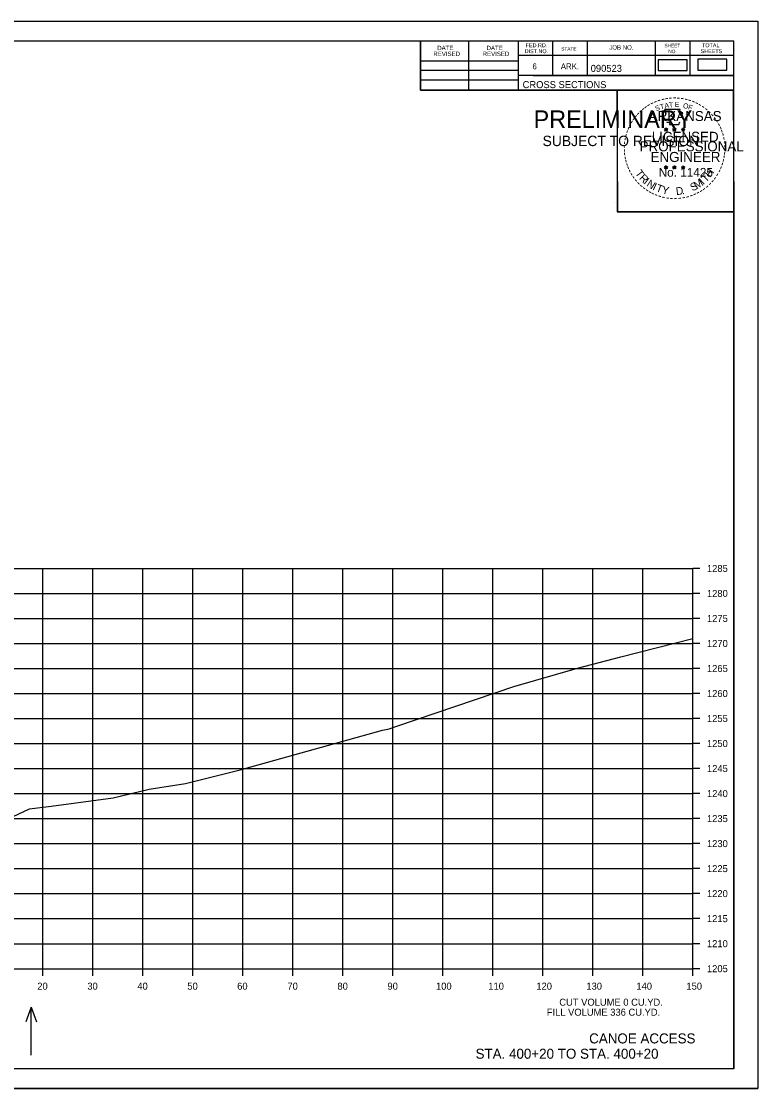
# Model space of a CAD drawing. Extents: x 1406028 to 1412453, y 321733 to 325986.
# Drawn here: x 1411799 to 1411946.2, y 322044.9 to 322258.3 of the extents above; entities that cross this region are included whole.
import ezdxf

# ---------------------------------------------------------------- set-up
doc = ezdxf.new("R2010")
doc.units = 0
for name, color, linetype in [('R_Axis', 7, 'Continuous'), ('R_Axis Annot', 7, 'Continuous'), ('R_Border', 7, 'Continuous'), ('R_Border PE', 7, 'Continuous'), ('R_Border Prem', 7, 'Continuous'), ('R_Draft', 7, 'Continuous'), ('R_Exist Surface', 7, 'Continuous'), ('R_Fin Surface', 7, 'Continuous'), ('R_Grid', 7, 'Continuous'), ('R_No Plot', 7, 'Continuous'), ('R_Water Annot', 7, 'Continuous')]:
    doc.layers.add(name, color=color, linetype=linetype)

msp = doc.modelspace()

# ---------------------------------------------------------------- linework, layer by layer
at = {"layer": 'R_Axis'}
for p, q in [((1411933.24, 322068.91), (1411933.24, 322148.91)), ((1411934.64, 322148.91), (1411933.24, 322148.91)), ((1411934.64, 322143.91), (1411933.24, 322143.91)), ((1411934.64, 322138.91), (1411933.24, 322138.91)), ((1411934.64, 322133.91), (1411933.24, 322133.91)), ((1411934.64, 322128.91), (1411933.24, 322128.91)), ((1411934.64, 322123.91), (1411933.24, 322123.91)), ((1411934.64, 322118.91), (1411933.24, 322118.91)), ((1411934.64, 322113.91), (1411933.24, 322113.91)), ((1411934.64, 322108.91), (1411933.24, 322108.91)), ((1411934.64, 322103.91), (1411933.24, 322103.91)), ((1411934.64, 322098.91), (1411933.24, 322098.91)), ((1411934.64, 322093.91), (1411933.24, 322093.91)), ((1411934.64, 322088.91), (1411933.24, 322088.91)), ((1411934.64, 322083.91), (1411933.24, 322083.91)), ((1411934.64, 322078.91), (1411933.24, 322078.91)), ((1411934.64, 322073.91), (1411933.24, 322073.91)), ((1411633.24, 322068.91), (1411933.24, 322068.91)), ((1411803.24, 322067.51), (1411803.24, 322068.91)), ((1411813.24, 322067.51), (1411813.24, 322068.91)), ((1411823.24, 322067.51), (1411823.24, 322068.91)), ((1411833.24, 322067.51), (1411833.24, 322068.91)), ((1411843.24, 322067.51), (1411843.24, 322068.91)), ((1411853.24, 322067.51), (1411853.24, 322068.91)), ((1411863.24, 322067.51), (1411863.24, 322068.91)), ((1411873.24, 322067.51), (1411873.24, 322068.91)), ((1411883.24, 322067.51), (1411883.24, 322068.91)), ((1411893.24, 322067.51), (1411893.24, 322068.91)), ((1411903.24, 322067.51), (1411903.24, 322068.91)), ((1411913.24, 322067.51), (1411913.24, 322068.91)), ((1411923.24, 322067.51), (1411923.24, 322068.91)), ((1411933.24, 322067.51), (1411933.24, 322068.91)), ((1411934.64, 322068.91), (1411933.24, 322068.91))]:
    msp.add_line(p, q, dxfattribs=at)
at = {"layer": 'R_Border'}
for p, q in [((1411625.24, 322254.37), (1411941.42, 322254.37)), ((1411878.78, 322244.49), (1411878.78, 322254.37)), ((1411888.46, 322244.49), (1411888.46, 322254.37)), ((1411898.32, 322254.37), (1411898.32, 322244.49)), ((1411905.16, 322254.37), (1411905.16, 322247.43)), ((1411912.1, 322254.37), (1411912.1, 322247.43)), ((1411925.68, 322254.37), (1411925.68, 322247.43)), ((1411932.62, 322254.37), (1411932.62, 322247.43)), ((1411941.42, 322048.91), (1411941.42, 322254.37)), ((1411941.42, 322251.43), (1411898.32, 322251.43)), ((1411941.42, 322251.45), (1411941.42, 322251.45)), ((1411878.78, 322250.35), (1411898.32, 322250.35)), ((1411878.78, 322248.49), (1411898.32, 322248.49)), ((1411878.78, 322246.55), (1411898.32, 322246.55)), ((1411941.42, 322247.43), (1411898.32, 322247.43)), ((1411901.28, 322247.43), (1411941.42, 322247.43)), ((1411941.42, 322244.49), (1411878.78, 322244.49)), ((1411941.42, 322048.91), (1411625.24, 322048.91))]:
    msp.add_line(p, q, dxfattribs=at)
at = {"layer": 'R_Border PE'}
for p, q in [((1411927.51, 322236.75), (1411927.86, 322236.64)), ((1411927.51, 322236.75), (1411927.76, 322236.7)), ((1411927.51, 322236.75), (1411927.75, 322236.63)), ((1411927.64, 322236.34), (1411927.86, 322236.64)), ((1411927.64, 322236.34), (1411927.77, 322236.58)), ((1411927.64, 322236.34), (1411927.86, 322236.56)), ((1411927.86, 322237), (1411927.82, 322236.75)), ((1411927.86, 322236.64), (1411927.86, 322237)), ((1411927.86, 322237), (1411927.91, 322236.75)), ((1411928.2, 322236.75), (1411927.86, 322236.64)), ((1411928.07, 322236.34), (1411927.86, 322236.64)), ((1411928.07, 322236.34), (1411927.86, 322236.55)), ((1411928.2, 322236.75), (1411927.92, 322236.7)), ((1411928.07, 322236.34), (1411927.93, 322236.63)), ((1411928.2, 322236.75), (1411928, 322236.65)), ((1411929.18, 322236.75), (1411929.53, 322236.64)), ((1411929.18, 322236.75), (1411929.43, 322236.7)), ((1411929.18, 322236.75), (1411929.42, 322236.63)), ((1411929.31, 322236.34), (1411929.53, 322236.64)), ((1411929.31, 322236.34), (1411929.44, 322236.58)), ((1411929.31, 322236.34), (1411929.53, 322236.56)), ((1411929.53, 322237), (1411929.49, 322236.75)), ((1411929.53, 322236.64), (1411929.53, 322237)), ((1411929.53, 322237), (1411929.58, 322236.75)), ((1411929.87, 322236.75), (1411929.53, 322236.64)), ((1411929.74, 322236.34), (1411929.53, 322236.64)), ((1411929.74, 322236.34), (1411929.53, 322236.55)), ((1411929.87, 322236.75), (1411929.59, 322236.7)), ((1411929.74, 322236.34), (1411929.6, 322236.63)), ((1411929.87, 322236.75), (1411929.67, 322236.65)), ((1411930.94, 322236.74), (1411931.29, 322236.62)), ((1411930.94, 322236.74), (1411931.2, 322236.69)), ((1411930.94, 322236.74), (1411931.18, 322236.61)), ((1411931.08, 322236.33), (1411931.29, 322236.62)), ((1411931.08, 322236.33), (1411931.2, 322236.57)), ((1411931.08, 322236.33), (1411931.29, 322236.54)), ((1411931.29, 322236.99), (1411931.25, 322236.74)), ((1411931.29, 322236.62), (1411931.29, 322236.99)), ((1411931.29, 322236.99), (1411931.34, 322236.74)), ((1411931.64, 322236.74), (1411931.29, 322236.62)), ((1411931.5, 322236.33), (1411931.29, 322236.62)), ((1411931.5, 322236.33), (1411931.29, 322236.54)), ((1411931.64, 322236.74), (1411931.35, 322236.69)), ((1411931.5, 322236.33), (1411931.37, 322236.62)), ((1411931.64, 322236.74), (1411931.43, 322236.63)), ((1411927.85, 322229.43), (1411927.81, 322229.18)), ((1411927.85, 322229.06), (1411927.85, 322229.43)), ((1411927.85, 322229.43), (1411927.9, 322229.18)), ((1411929.52, 322229.43), (1411929.48, 322229.18)), ((1411929.52, 322229.06), (1411929.52, 322229.43)), ((1411929.52, 322229.43), (1411929.57, 322229.18)), ((1411931.29, 322229.42), (1411931.25, 322229.17)), ((1411931.29, 322229.05), (1411931.29, 322229.42)), ((1411931.29, 322229.42), (1411931.34, 322229.17)), ((1411927.5, 322229.17), (1411927.85, 322229.06)), ((1411927.5, 322229.17), (1411927.76, 322229.13)), ((1411927.5, 322229.17), (1411927.74, 322229.05)), ((1411927.64, 322228.77), (1411927.85, 322229.06)), ((1411927.64, 322228.77), (1411927.76, 322229.01)), ((1411927.64, 322228.77), (1411927.85, 322228.98)), ((1411928.2, 322229.17), (1411927.85, 322229.06)), ((1411928.07, 322228.77), (1411927.85, 322229.06)), ((1411928.07, 322228.77), (1411927.85, 322228.98)), ((1411928.2, 322229.17), (1411927.91, 322229.13)), ((1411928.07, 322228.77), (1411927.93, 322229.06)), ((1411928.2, 322229.17), (1411928, 322229.07)), ((1411929.17, 322229.17), (1411929.52, 322229.06)), ((1411929.17, 322229.17), (1411929.43, 322229.13)), ((1411929.17, 322229.17), (1411929.41, 322229.05)), ((1411929.31, 322228.77), (1411929.52, 322229.06)), ((1411929.31, 322228.77), (1411929.43, 322229.01)), ((1411929.31, 322228.77), (1411929.52, 322228.98)), ((1411929.87, 322229.17), (1411929.52, 322229.06)), ((1411929.74, 322228.77), (1411929.52, 322229.06)), ((1411929.74, 322228.77), (1411929.52, 322228.98)), ((1411929.87, 322229.17), (1411929.58, 322229.13)), ((1411929.74, 322228.77), (1411929.6, 322229.06)), ((1411929.87, 322229.17), (1411929.67, 322229.07)), ((1411930.94, 322229.16), (1411931.29, 322229.05)), ((1411930.94, 322229.16), (1411931.19, 322229.12)), ((1411930.94, 322229.16), (1411931.18, 322229.04)), ((1411931.07, 322228.76), (1411931.29, 322229.05)), ((1411931.07, 322228.76), (1411931.2, 322229)), ((1411931.07, 322228.76), (1411931.29, 322228.97)), ((1411931.64, 322229.16), (1411931.29, 322229.05)), ((1411931.5, 322228.76), (1411931.29, 322229.05)), ((1411931.5, 322228.76), (1411931.29, 322228.97)), ((1411931.64, 322229.16), (1411931.35, 322229.12)), ((1411931.5, 322228.76), (1411931.37, 322229.05)), ((1411931.64, 322229.16), (1411931.43, 322229.06))]:
    msp.add_line(p, q, dxfattribs=at)
for points in [[(1411927.55, 322240.63), (1411927.82, 322239.8)], [(1411931.06, 322239.7), (1411931.2, 322239.99), (1411930.52, 322239.96), (1411930.67, 322240.63), (1411927.55, 322240.63)], [(1411928.04, 322238.2), (1411928.04, 322238.12), (1411928.6, 322238.1), (1411928.55, 322237.62), (1411930.42, 322237.62), (1411930.62, 322238.16)], [(1411927.86, 322237), (1411928.07, 322236.34), (1411927.51, 322236.75), (1411928.2, 322236.75), (1411927.64, 322236.34), (1411927.86, 322237)], [(1411929.53, 322237), (1411929.74, 322236.34), (1411929.18, 322236.75), (1411929.87, 322236.75), (1411929.31, 322236.34), (1411929.53, 322237)], [(1411931.29, 322236.99), (1411931.5, 322236.33), (1411930.94, 322236.74), (1411931.64, 322236.74), (1411931.08, 322236.33), (1411931.29, 322236.99)], [(1411927.85, 322229.43), (1411928.07, 322228.77), (1411927.5, 322229.17), (1411928.2, 322229.17), (1411927.64, 322228.77), (1411927.85, 322229.43)], [(1411929.52, 322229.43), (1411929.74, 322228.77), (1411929.17, 322229.17), (1411929.87, 322229.17), (1411929.31, 322228.77), (1411929.52, 322229.43)], [(1411931.29, 322229.42), (1411931.5, 322228.76), (1411930.94, 322229.16), (1411931.64, 322229.16), (1411931.07, 322228.76), (1411931.29, 322229.42)]]:
    msp.add_lwpolyline(points, dxfattribs=at)
for centre, radius in [((1411927.86, 322236.64), 0.172), ((1411927.86, 322236.64), 0.145), ((1411927.86, 322236.64), 0.116), ((1411927.86, 322236.64), 0.0991), ((1411927.86, 322236.64), 0.0747), ((1411927.86, 322236.64), 0.0495), ((1411927.86, 322236.64), 0.0296), ((1411929.53, 322236.64), 0.172), ((1411929.53, 322236.64), 0.145), ((1411929.53, 322236.64), 0.116), ((1411929.53, 322236.64), 0.0991), ((1411929.53, 322236.64), 0.0747), ((1411929.53, 322236.64), 0.0495), ((1411929.53, 322236.64), 0.0296), ((1411931.29, 322236.62), 0.172), ((1411931.29, 322236.62), 0.145), ((1411931.29, 322236.62), 0.116), ((1411931.29, 322236.62), 0.0991), ((1411931.29, 322236.62), 0.0747), ((1411931.29, 322236.62), 0.0495), ((1411931.29, 322236.62), 0.0296), ((1411927.85, 322229.06), 0.172), ((1411927.85, 322229.06), 0.145), ((1411927.85, 322229.06), 0.116), ((1411927.85, 322229.06), 0.0991), ((1411927.85, 322229.06), 0.0747), ((1411927.85, 322229.06), 0.0495), ((1411927.85, 322229.06), 0.0296), ((1411929.52, 322229.06), 0.172), ((1411929.52, 322229.06), 0.145), ((1411929.52, 322229.06), 0.116), ((1411929.52, 322229.06), 0.0991), ((1411929.52, 322229.06), 0.0747), ((1411929.52, 322229.06), 0.0495), ((1411929.52, 322229.06), 0.0296), ((1411931.29, 322229.05), 0.172), ((1411931.29, 322229.05), 0.145), ((1411931.29, 322229.05), 0.116), ((1411931.29, 322229.05), 0.0991), ((1411931.29, 322229.05), 0.0747), ((1411931.29, 322229.05), 0.0495), ((1411931.29, 322229.05), 0.0296)]:
    msp.add_circle(centre, radius, dxfattribs=at)
at = {"layer": 'R_Exist Surface'}
msp.add_lwpolyline([(1411786.04, 322094.07), (1411800.57, 322100.83), (1411804.9, 322101.41), (1411817.35, 322103.05), (1411824.51, 322104.81), (1411831.82, 322105.92), (1411842.7, 322108.67), (1411871.19, 322116.61), (1411872.21, 322116.81), (1411872.49, 322116.86), (1411874.06, 322117.41), (1411897.46, 322125.32), (1411910.16, 322128.99), (1411918.81, 322131.24), (1411933.24, 322134.92)], dxfattribs=at)
at = {"layer": 'R_Fin Surface'}
for points in [[(1411934.19, 322248.54), (1411940.02, 322248.54), (1411940.02, 322250.73), (1411934.19, 322250.73)], [(1411926.28, 322248.42), (1411932.11, 322248.42), (1411932.11, 322250.6), (1411926.28, 322250.6)]]:
    msp.add_lwpolyline(points, close=True, dxfattribs=at)
at = {"layer": 'R_Grid'}
for p, q in [((1411633.24, 322148.91), (1411933.24, 322148.91)), ((1411803.24, 322068.91), (1411803.24, 322148.91)), ((1411813.24, 322068.91), (1411813.24, 322148.91)), ((1411823.24, 322068.91), (1411823.24, 322148.91)), ((1411833.24, 322068.91), (1411833.24, 322148.91)), ((1411843.24, 322068.91), (1411843.24, 322148.91)), ((1411853.24, 322068.91), (1411853.24, 322148.91)), ((1411863.24, 322068.91), (1411863.24, 322148.91)), ((1411873.24, 322068.91), (1411873.24, 322148.91)), ((1411883.24, 322068.91), (1411883.24, 322148.91)), ((1411893.24, 322068.91), (1411893.24, 322148.91)), ((1411903.24, 322068.91), (1411903.24, 322148.91)), ((1411913.24, 322068.91), (1411913.24, 322148.91)), ((1411923.24, 322068.91), (1411923.24, 322148.91)), ((1411933.24, 322068.91), (1411933.24, 322148.91)), ((1411633.24, 322143.91), (1411933.24, 322143.91)), ((1411633.24, 322138.91), (1411933.24, 322138.91)), ((1411633.24, 322133.91), (1411933.24, 322133.91)), ((1411633.24, 322128.91), (1411933.24, 322128.91)), ((1411633.24, 322123.91), (1411933.24, 322123.91)), ((1411633.24, 322118.91), (1411933.24, 322118.91)), ((1411633.24, 322113.91), (1411933.24, 322113.91)), ((1411633.24, 322108.91), (1411933.24, 322108.91)), ((1411633.24, 322103.91), (1411933.24, 322103.91)), ((1411633.24, 322098.91), (1411933.24, 322098.91)), ((1411633.24, 322093.91), (1411933.24, 322093.91)), ((1411633.24, 322088.91), (1411933.24, 322088.91)), ((1411633.24, 322083.91), (1411933.24, 322083.91)), ((1411633.24, 322078.91), (1411933.24, 322078.91)), ((1411633.24, 322073.91), (1411933.24, 322073.91)), ((1411633.24, 322068.91), (1411933.24, 322068.91))]:
    msp.add_line(p, q, dxfattribs=at)
at = {"layer": 'R_No Plot'}
for p, q in [((1411612.84, 322258.27), (1411946.18, 322258.27)), ((1411917.46, 322222.04), (1411917.46, 322222.04)), ((1411612.84, 322044.93), (1411946.18, 322044.93))]:
    msp.add_line(p, q, dxfattribs=at)
for points in [[(1411612.84, 322258.27), (1411946.18, 322258.27), (1411946.18, 322044.93), (1411612.84, 322044.93)], [(1411859.16, 322254.37), (1411878.78, 322254.37), (1411878.78, 322244.49), (1411894.9, 322244.49), (1411918.1, 322244.49), (1411918.1, 322220.16), (1411941.42, 322220.16), (1411941.42, 322048.91), (1411625.24, 322048.91), (1411625.24, 322254.37)], [(1411918.1, 322244.49), (1411941.3, 322244.49), (1411941.42, 322220.16), (1411918.22, 322220.16)]]:
    msp.add_lwpolyline(points, close=True, dxfattribs=at)
at = {"layer": 'R_Water Annot'}
for p, q in [((1411800.93, 322061.19), (1411799.87, 322058.26)), ((1411800.93, 322051.61), (1411800.93, 322061.19)), ((1411800.93, 322061.19), (1411802, 322058.26))]:
    msp.add_line(p, q, dxfattribs=at)

# ---------------------------------------------------------------- texts
at = {"layer": 'R_Axis Annot'}
for s, p in [('1285', (1411936.04, 322148.21)), ('1280', (1411936.04, 322143.21)), ('1275', (1411936.04, 322138.21)), ('1270', (1411936.04, 322133.21)), ('1265', (1411936.04, 322128.21)), ('1260', (1411936.04, 322123.21)), ('1255', (1411936.04, 322118.21)), ('1250', (1411936.04, 322113.21)), ('1245', (1411936.04, 322108.21)), ('1240', (1411936.04, 322103.21)), ('1235', (1411936.04, 322098.21)), ('1230', (1411936.04, 322093.21)), ('1225', (1411936.04, 322088.21)), ('1220', (1411936.04, 322083.21)), ('1215', (1411936.04, 322078.21)), ('1210', (1411936.04, 322073.21)), ('1205', (1411936.04, 322068.21)), ('20', (1411802.16, 322064.71)), ('30', (1411812.16, 322064.71)), ('40', (1411822.16, 322064.71)), ('50', (1411832.16, 322064.71)), ('60', (1411842.12, 322064.71)), ('70', (1411852.16, 322064.71)), ('80', (1411862.16, 322064.71)), ('90', (1411872.16, 322064.71)), ('100', (1411881.87, 322064.71)), ('110', (1411892.32, 322064.71)), ('120', (1411901.93, 322064.71)), ('130', (1411911.93, 322064.71)), ('140', (1411921.93, 322064.71)), ('150', (1411931.93, 322064.71)), ('FILL VOLUME 336 CU.YD.', (1411904.01, 322059.51)), ('CUT VOLUME 0 CU.YD.', (1411906.52, 322061.51))]:
    msp.add_text(s, height=1.4, dxfattribs=at).set_placement(p)
at = {"layer": 'R_Border'}
for s, height, p in [('DATE', 0.879, (1411882.12, 322252.51)), ('DATE', 0.879, (1411891.98, 322252.51)), ('FED.RD.', 0.782, (1411899.8, 322253.09)), ('STATE', 0.684, (1411906.92, 322252.41)), ('JOB NO.', 0.879, (1411916.5, 322252.61)), ('SHEET', 0.684, (1411927.54, 322253.09)), ('TOTAL', 0.782, (1411935.06, 322253.09)), ('REVISED', 0.879, (1411881.34, 322251.33)), ('REVISED', 0.879, (1411891.2, 322251.33)), ('DIST.NO.', 0.782, (1411899.6, 322251.91)), ('NO.', 0.684, (1411928.32, 322251.91)), ('SHEETS', 0.782, (1411934.78, 322251.91)), ('6', 1.17, (1411901.16, 322248.69)), ('ARK.', 1.172, (1411906.82, 322248.69)), ('090523', 1.4, (1411912.8, 322248.17)), ('CROSS SECTIONS', 1.4, (1411899.19, 322244.92))]:
    msp.add_text(s, height=height, rotation=360, dxfattribs=at).set_placement(p)
at = {"layer": 'R_Border PE'}
for s, height, rotation, p in [('-', 1.6, 24.3072, (1411925.66, 322241.48)), ('-', 1.6, 19.1761, (1411926.3, 322241.75)), ('-', 1.6, 13.6301, (1411927.05, 322241.99)), ('-', 1.6, 10.2193, (1411927.73, 322242.16)), ('-', 1.6, 5.8968, (1411928.45, 322242.27)), ('-', 1.6, 0.1862, (1411929.23, 322242.34)), ('-', 1.6, 357.743, (1411929.95, 322242.32)), ('-', 1.6, 352.1617, (1411930.69, 322242.27)), ('-', 1.6, 347.2049, (1411931.41, 322242.15)), ('-', 1.6, 342.3362, (1411932.05, 322242)), ('-', 1.6, 337.8551, (1411932.78, 322241.78)), ('-', 1.6, 48.423, (1411922.5, 322239.13)), ('-', 1.6, 42.9622, (1411922.95, 322239.61)), ('-', 1.6, 38.9507, (1411923.38, 322240.02)), ('-', 1.6, 36.2317, (1411923.86, 322240.4)), ('-', 1.6, 34.0636, (1411924.43, 322240.8)), ('ARKANSAS', 2, 360, (1411924.4, 322238.34)), ('-', 1.6, 28.7918, (1411925.03, 322241.17)), ('S', 1, 21.594, (1411925.9, 322240.3)), ('T', 1, 16.4036, (1411926.82, 322240.63)), ('A', 1, 11.2132, (1411927.64, 322240.89)), ('T', 1, 6.0228, (1411928.49, 322241.05)), ('E', 1, 0.8323, (1411929.6, 322241.16)), ('O', 1, 350.4515, (1411931.2, 322240.95)), ('F', 1, 340.0707, (1411932.16, 322240.72)), ('-', 1.6, 334.1211, (1411933.41, 322241.51)), ('-', 1.6, 329.6409, (1411933.99, 322241.22)), ('-', 1.6, 325.8627, (1411934.64, 322240.86)), ('-', 1.6, 320.5297, (1411935.25, 322240.44)), ('-', 1.6, 315.5786, (1411935.84, 322239.95)), ('-', 1.6, 58.0706, (1411921.36, 322237.55)), ('-', 1.6, 54.2325, (1411921.68, 322238.08)), ('-', 1.6, 50.6142, (1411922.1, 322238.64)), ('-', 1.6, 309.8797, (1411936.41, 322239.4)), ('-', 1.6, 306.6522, (1411936.94, 322238.8)), ('-', 1.4, 303.6753, (1411937.42, 322238.23)), ('-', 1.6, 72.3945, (1411920.57, 322235.69)), ('-', 1.6, 67.7743, (1411920.79, 322236.32)), ('-', 1.6, 62.8713, (1411921.04, 322236.93)), ('LICENSED', 2, 360, (1411925, 322234.19)), ('DWB', 0.01, 360, (1411927.84, 322236.63)), ('DWB', 0.01, 360, (1411929.51, 322236.63)), ('DWB', 0.01, 360, (1411931.28, 322236.62)), ('-', 1.6, 299.6684, (1411937.74, 322237.62)), ('-', 1.6, 294.6628, (1411938.07, 322237.01)), ('-', 1.6, 290.5728, (1411938.32, 322236.43)), ('-', 1.6, 285.1233, (1411938.56, 322235.85)), ('-', 1.6, 85.1863, (1411920.16, 322233.58)), ('-', 1.6, 81.2013, (1411920.24, 322234.27)), ('-', 1.6, 75.461, (1411920.37, 322234.98)), ('PROFESSIONAL', 2, 360, (1411922.58, 322232.28)), ('-', 1.6, 280.5493, (1411938.76, 322235.11)), ('-', 1.6, 276.5962, (1411938.92, 322234.34)), ('-', 1.6, 94.1959, (1411920.17, 322232.15)), ('-', 1.6, 89.0622, (1411920.14, 322232.87)), ('-', 1.6, 98.9479, (1411920.24, 322231.48)), ('ENGINEER', 2, 360, (1411924.76, 322230.16)), ('-', 1.6, 263.5172, (1411939, 322232.32)), ('-', 1.6, 274.3301, (1411938.98, 322233.62)), ('-', 1.6, 269.9407, (1411939.01, 322232.99)), ('-', 1.6, 101.7149, (1411920.38, 322230.75)), ('-', 1.6, 105.4578, (1411920.54, 322230.15)), ('-', 1.6, 109.0874, (1411920.76, 322229.52)), ('-', 1.6, 252.8681, (1411938.63, 322230.27)), ('-', 1.6, 255.7626, (1411938.81, 322230.99)), ('-', 1.6, 260.9953, (1411938.92, 322231.67)), ('-', 1.6, 114.0643, (1411921.01, 322228.93)), ('-', 1.6, 115.7289, (1411921.31, 322228.31)), ('-', 1.6, 120.4471, (1411921.67, 322227.72)), ('-', 1.6, 125.8934, (1411922.07, 322227.16)), ('T', 1.54, 306.0406, (1411921.61, 322227.9)), ('R', 1.54, 314.005, (1411922.38, 322226.85)), ('No. 11425', 1.757, 360, (1411926.39, 322227.21)), ('DWB', 0.01, 360, (1411927.84, 322229.06)), ('DWB', 0.01, 360, (1411929.51, 322229.06)), ('DWB', 0.01, 360, (1411931.28, 322229.05)), ('T', 1.54, 46.6444, (1411935.84, 322225.99)), ('H', 1.54, 54.6088, (1411936.73, 322226.94)), ('-', 1.6, 239.0712, (1411937.75, 322228.22)), ('-', 1.6, 244.6197, (1411938.15, 322228.97)), ('-', 1.6, 247.8887, (1411938.41, 322229.6)), ('-', 1.6, 130.7181, (1411922.54, 322226.61)), ('-', 1.6, 134.2238, (1411923.05, 322226.07)), ('-', 1.6, 138.9338, (1411923.58, 322225.6)), ('-', 1.6, 144.6463, (1411924.13, 322225.2)), ('I', 1.54, 321.9694, (1411923.28, 322225.92)), ('N', 1.54, 326.5002, (1411923.84, 322225.45)), ('I', 1.54, 335.3603, (1411925.05, 322224.66)), ('T', 1.54, 339.8912, (1411925.71, 322224.34)), ('Y', 1.54, 347.8556, (1411926.93, 322223.89)), ('D', 1.54, 6.3969, (1411929.91, 322223.53)), ('S', 1.54, 26.9312, (1411933.16, 322224.26)), ('M', 1.54, 32.6563, (1411934, 322224.67)), ('I', 1.54, 42.1136, (1411935.28, 322225.52)), ('-', 1.6, 221.0851, (1411935.92, 322225.92)), ('-', 1.6, 225.7653, (1411936.44, 322226.43)), ('-', 1.6, 231.2538, (1411936.92, 322227)), ('-', 1.6, 233.8452, (1411937.35, 322227.56)), ('-', 1.6, 148.0898, (1411924.7, 322224.82)), ('-', 1.6, 151.5704, (1411925.27, 322224.5)), ('-', 1.6, 154.6002, (1411925.8, 322224.25)), ('-', 1.6, 158.5612, (1411926.42, 322224)), ('-', 1.6, 162.7983, (1411927.11, 322223.79)), ('-', 1.6, 167.5555, (1411927.82, 322223.62)), ('-', 1.6, 173.1155, (1411928.59, 322223.51)), ('-', 1.6, 185.8167, (1411930.9, 322223.55)), ('-', 1.6, 191.2858, (1411931.63, 322223.69)), ('.', 1.54, 13.7642, (1411931.11, 322223.66)), ('-', 1.6, 195.4743, (1411932.36, 322223.88)), ('-', 1.6, 200.7184, (1411933.04, 322224.13)), ('-', 1.6, 204.2516, (1411933.66, 322224.4)), ('-', 1.6, 207.3568, (1411934.28, 322224.72)), ('-', 1.6, 212.2491, (1411934.84, 322225.06)), ('-', 1.6, 215.7363, (1411935.37, 322225.45)), ('-', 1.6, 176.5183, (1411929.34, 322223.46)), ('-', 1.6, 181.5918, (1411930.09, 322223.48))]:
    msp.add_text(s, height=height, rotation=rotation, dxfattribs=at).set_placement(p)
at = {"layer": 'R_Border Prem'}
for s, height, p in [('PRELIMINARY', 3.5, (1411901.38, 322236.96)), ('DWB', 0.01, (1411902.12, 322238.81)), ('SUBJECT TO REVISION', 2.0751, (1411903.18, 322233.33))]:
    msp.add_text(s, height=height, rotation=360, dxfattribs=at).set_placement(p)
at = {"layer": 'R_Draft'}
for s, p in [('CANOE ACCESS', (1411912.49, 322053.97)), ('STA. 400+20 TO STA. 400+20', (1411889.78, 322050.91))]:
    msp.add_text(s, height=2, dxfattribs=at).set_placement(p)

doc.saveas('drawing.dxf')
